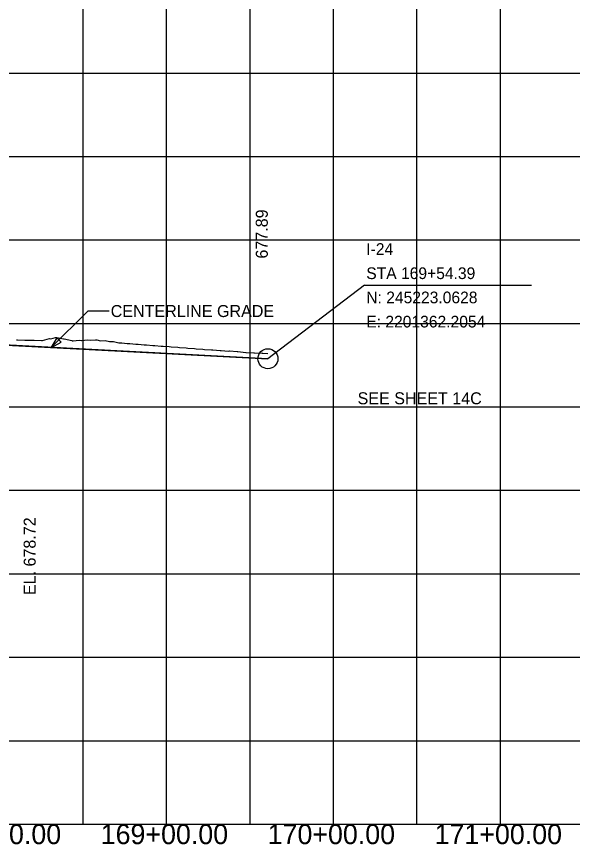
# Model space of a CAD drawing. Extents: x -7164 to 2214450, y -19642 to 253469.
# Drawn here: x 10810.1 to 11143.1, y -3012.2 to -2516.1 of the extents above; entities that cross this region are included whole.
import ezdxf

# ---------------------------------------------------------------- set-up
doc = ezdxf.new("R2010")
doc.units = 0
for name, color, linetype in [('DESIGN - PROFILE - Proposed', 7, 'Continuous'), ('DESIGN - PROFILE - Proposed Curve Text', 7, 'Continuous'), ('DESIGN - PROFILE - Proposed Text', 7, 'Continuous'), ('DESIGN - SCRATCH - User 1', 7, 'Continuous'), ('DESIGN - SCRATCH - User 2', 7, 'Continuous'), ('DESIGN - SHEET - Light Grid', 7, 'Continuous'), ('SURVEY - PROFILE - Ground Line with Text', 7, 'Continuous'), ('XTREE', 7, 'Continuous')]:
    doc.layers.add(name, color=color, linetype=linetype)

msp = doc.modelspace()

# ---------------------------------------------------------------- linework, layer by layer
at = {"layer": 'DESIGN - PROFILE - Proposed'}
msp.add_line((10800, -2712.77), (10960.7, -2721.15), dxfattribs=at)
msp.add_line((10800, -2712.77), (10960.7, -2721.15), dxfattribs=at)
at = {"layer": 'DESIGN - PROFILE - Proposed Text'}
msp.add_line((11018.62, -2677.18), (11118.62, -2677.18), dxfattribs=at)
msp.add_line((11018.62, -2677.18), (11118.62, -2677.18), dxfattribs=at)
for points in [[(11018.62, -2677.18), (10960.7, -2721.15)], [(11018.62, -2677.18), (10960.7, -2721.15)], [(10865.54, -2692.58), (10852.74, -2692.58), (10830.74, -2714.66)], [(10865.54, -2692.58), (10852.74, -2692.58), (10830.74, -2714.66)]]:
    msp.add_lwpolyline(points, dxfattribs=at)
msp.add_lwpolyline([(10834.23, -2708.59), (10830.74, -2714.66), (10836.79, -2711.15)], close=True, dxfattribs=at)
msp.add_lwpolyline([(10834.23, -2708.59), (10830.74, -2714.66), (10836.79, -2711.15)], close=True, dxfattribs=at)
msp.add_circle((10960.7, -2721.15), 6, dxfattribs=at)
msp.add_circle((10960.7, -2721.15), 6, dxfattribs=at)
at = {"layer": 'DESIGN - SCRATCH - User 1'}
msp.add_line((0, -3000), (12400, -3000), dxfattribs=at)
msp.add_line((0, -3000), (12400, -3000), dxfattribs=at)
at = {"layer": 'DESIGN - SHEET - Light Grid'}
for p, q in [((10850, -3000), (10850, -1000)), ((10850, -3000), (10850, -1000)), ((10900, -3000), (10900, -1000)), ((10900, -3000), (10900, -1000)), ((10950, -3000), (10950, -1000)), ((10950, -3000), (10950, -1000)), ((11000, -3000), (11000, -1000)), ((11000, -3000), (11000, -1000)), ((11050, -3000), (11050, -1000)), ((11050, -3000), (11050, -1000)), ((11100, -3000), (11100, -1000)), ((11100, -3000), (11100, -1000)), ((0, -2550), (12400, -2550)), ((0, -2550), (12400, -2550)), ((0, -2600), (12400, -2600)), ((0, -2600), (12400, -2600)), ((0, -2650), (12400, -2650)), ((0, -2650), (12400, -2650)), ((0, -2700), (12400, -2700)), ((0, -2700), (12400, -2700)), ((0, -2750), (12400, -2750)), ((0, -2750), (12400, -2750)), ((0, -2800), (12400, -2800)), ((0, -2800), (12400, -2800)), ((0, -2850), (12400, -2850)), ((0, -2850), (12400, -2850)), ((0, -2900), (12400, -2900)), ((0, -2900), (12400, -2900)), ((0, -2950), (12400, -2950)), ((0, -2950), (12400, -2950)), ((-1000, -3000), (11000, -3000)), ((-1000, -3000), (11000, -3000))]:
    msp.add_line(p, q, dxfattribs=at)
at = {"layer": 'SURVEY - PROFILE - Ground Line with Text'}
for points in [[(10810.13, -2709.85), (10810.61, -2709.86), (10815.09, -2709.97), (10815.62, -2709.98), (10820.06, -2710.09), (10820.63, -2710.1), (10825.02, -2710.2), (10825.64, -2710.22), (10825.66, -2710.22), (10829.97, -2709.12), (10830.67, -2709.14), (10833.55, -2708.42), (10834.3, -2708.44), (10838.31, -2709.29), (10838.75, -2709.3), (10843.35, -2710.33), (10843.41, -2710.34), (10844.1, -2710.5), (10847.73, -2709.94), (10848.86, -2710.17), (10848.95, -2710.16), (10852.57, -2709.74), (10854.14, -2710.01), (10857.42, -2709.74), (10857.94, -2709.83), (10858.28, -2709.9), (10860.34, -2710.35), (10863.24, -2710.24), (10865.84, -2710.87), (10868.2, -2710.85), (10871.31, -2711.67), (10873.16, -2711.71), (10876.39, -2712.03), (10878.02, -2712.03), (10881.51, -2712.38), (10883.01, -2712.39), (10886.61, -2712.75), (10888, -2712.77), (10891.71, -2713.14), (10892.99, -2713.17), (10896.79, -2713.55), (10897.98, -2713.58), (10901.62, -2713.89), (10902.73, -2713.95), (10906.65, -2714.28), (10907.72, -2714.34), (10911.68, -2714.68)], [(10810.13, -2709.85), (10810.61, -2709.86), (10815.09, -2709.97), (10815.62, -2709.98), (10820.06, -2710.09), (10820.63, -2710.1), (10825.02, -2710.2), (10825.64, -2710.22), (10825.66, -2710.22), (10829.97, -2709.12), (10830.67, -2709.14), (10833.55, -2708.42), (10834.3, -2708.44), (10838.31, -2709.29), (10838.75, -2709.3), (10843.35, -2710.33), (10843.41, -2710.34), (10844.1, -2710.5), (10847.73, -2709.94), (10848.86, -2710.17), (10848.95, -2710.16), (10852.57, -2709.74), (10854.14, -2710.01), (10857.42, -2709.74), (10857.94, -2709.83), (10858.28, -2709.9), (10860.34, -2710.35), (10863.24, -2710.24), (10865.84, -2710.87), (10868.2, -2710.85), (10871.31, -2711.67), (10873.16, -2711.71), (10876.39, -2712.03), (10878.02, -2712.03), (10881.51, -2712.38), (10883.01, -2712.39), (10886.61, -2712.75), (10888, -2712.77), (10891.71, -2713.14), (10892.99, -2713.17), (10896.79, -2713.55), (10897.98, -2713.58), (10901.62, -2713.89), (10902.73, -2713.95), (10906.65, -2714.28), (10907.72, -2714.34), (10911.68, -2714.68)], [(10911.68, -2714.68), (10912.72, -2714.73), (10916.71, -2715.07), (10917.71, -2715.13), (10921.74, -2715.47), (10922.71, -2715.53), (10922.73, -2715.53), (10926.89, -2715.84), (10927.71, -2715.83), (10932.02, -2716.17), (10932.69, -2716.16), (10937.15, -2716.53), (10937.66, -2716.52), (10942.29, -2716.92), (10942.64, -2716.91), (10947.44, -2717.34), (10947.61, -2717.34), (10952.32, -2717.59), (10952.62, -2717.6), (10957.21, -2717.84), (10957.63, -2717.84), (10960.7, -2718)], [(10911.68, -2714.68), (10912.72, -2714.73), (10916.71, -2715.07), (10917.71, -2715.13), (10921.74, -2715.47), (10922.71, -2715.53), (10922.73, -2715.53), (10926.89, -2715.84), (10927.71, -2715.83), (10932.02, -2716.17), (10932.69, -2716.16), (10937.15, -2716.53), (10937.66, -2716.52), (10942.29, -2716.92), (10942.64, -2716.91), (10947.44, -2717.34), (10947.61, -2717.34), (10952.32, -2717.59), (10952.62, -2717.6), (10957.21, -2717.84), (10957.63, -2717.84), (10960.7, -2718)]]:
    msp.add_lwpolyline(points, dxfattribs=at)
at = {"layer": 'XTREE'}
msp.add_line((10960.7, -2721.15), (10550, -2699.73), dxfattribs=at)
msp.add_line((10960.7, -2721.15), (10550, -2699.73), dxfattribs=at)

# ---------------------------------------------------------------- texts
at = {"layer": 'DESIGN - PROFILE - Proposed Curve Text'}
msp.add_text('677.89', height=7.2, rotation=90, dxfattribs=at).set_placement((10960.63, -2661.15))
msp.add_text('677.89', height=7.2, rotation=90, dxfattribs=at).set_placement((10960.63, -2661.15))
at = {"layer": 'DESIGN - PROFILE - Proposed Text'}
for s, height, p in [('I-24', 7, (11019.62, -2658.93)), ('I-24', 7, (11019.62, -2658.93)), ('STA 169+54.39', 7, (11019.62, -2673.43)), ('STA 169+54.39', 7, (11019.62, -2673.43)), ('N: 245223.0628', 7, (11019.62, -2687.93)), ('N: 245223.0628', 7, (11019.62, -2687.93)), ('CENTERLINE GRADE', 7.2, (10866.54, -2696.18)), ('CENTERLINE GRADE', 7.2, (10866.54, -2696.18)), ('E: 2201362.2054', 7, (11019.62, -2702.43)), ('E: 2201362.2054', 7, (11019.62, -2702.43)), ('SEE SHEET 14C', 7.2, (11014.43, -2748.47)), ('SEE SHEET 14C', 7.2, (11014.43, -2748.47))]:
    msp.add_text(s, height=height, dxfattribs=at).set_placement(p)
msp.add_text('EL. 678.72', height=7.2, rotation=90, dxfattribs=at).set_placement((10821.6, -2862.77))
msp.add_text('EL. 678.72', height=7.2, rotation=90, dxfattribs=at).set_placement((10821.6, -2862.77))
at = {"layer": 'DESIGN - SCRATCH - User 2'}
for s, p in [('168+00.00', (10760.56, -3012)), ('169+00.00', (10860.56, -3012)), ('170+00.00', (10960.56, -3012)), ('171+00.00', (11060.56, -3012))]:
    msp.add_text(s, height=12, dxfattribs=at).set_placement(p)

doc.saveas('drawing.dxf')
